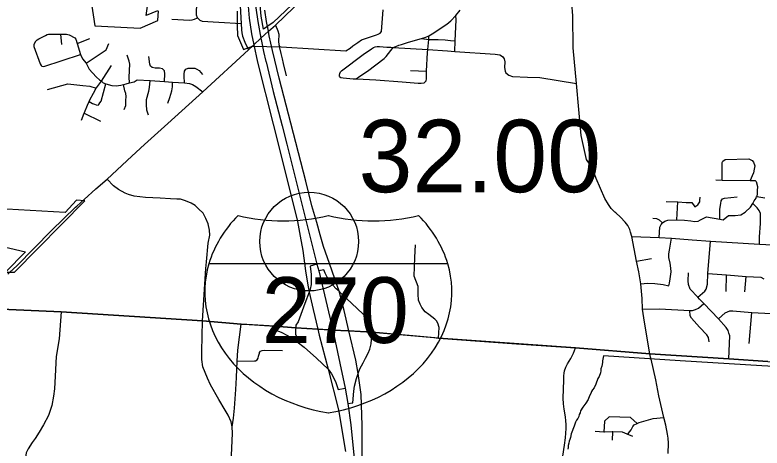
# Model space of a CAD drawing. Extents: x 1659811 to 1934326, y 644115 to 934867.
# Drawn here: x 1850731 to 1862074, y 747771 to 754351 of the extents above; entities that cross this region are included whole.
import ezdxf

# ---------------------------------------------------------------- set-up
doc = ezdxf.new("R2010")
doc.units = 0
for name, color, linetype in [('Default', 7, 'Continuous'), ('GM_X_City_Street', 7, 'Continuous'), ('GM_X_Corporation', 7, 'Continuous'), ('GM_X_County_Road', 7, 'Continuous'), ('GM_X_Interchange_Ramps', 7, 'Continuous'), ('GM_X_Interstate_Route', 7, 'Continuous'), ('GM_X_Interstate_Shield', 7, 'Continuous'), ('GM_X_Township', 7, 'Continuous'), ('GM_X_Township_Road', 7, 'Continuous')]:
    doc.layers.add(name, color=color, linetype=linetype)

msp = doc.modelspace()

# ---------------------------------------------------------------- linework, layer by layer
at = {"layer": 'Default'}
msp.add_circle((1855198, 750908), 750, dxfattribs=at)
at = {"layer": 'GM_X_City_Street'}
for points in [[(1853501, 754308), (1853490, 754346), (1853488, 754401), (1853507, 754810)], [(1859454, 752088), (1859408, 752155), (1859329, 752517), (1859255, 753310), (1859205, 753850), (1859199, 754339), (1859170, 754729)], [(1855660, 753415), (1855658, 753435), (1855662, 753460), (1855674, 753485), (1855687, 753500), (1856020, 753750), (1856142, 753838), (1856175, 753856), (1856201, 753864), (1856231, 753871), (1856267, 753873), (1856375, 753863), (1856437, 753860), (1856475, 753856), (1856514, 753870), (1856561, 753891), (1856600, 753902), (1856706, 753937), (1856905, 753992), (1856971, 754015), (1857017, 754034), (1857063, 754065), (1857290, 754210), (1857351, 754263), (1857423, 754341), (1857489, 754425)], [(1853113, 754289), (1853379, 754274), (1853424, 754276), (1853458, 754288), (1853501, 754308)], [(1853501, 754308), (1853536, 754272), (1853575, 754257), (1853826, 754241), (1854164, 754221)], [(1857407, 753798), (1857413, 753956), (1857431, 754277), (1857423, 754341)], [(1851037, 753940), (1851069, 753975), (1851092, 753990), (1851196, 754040), (1851218, 754052), (1851239, 754059), (1851416, 754060), (1851430, 754060), (1851450, 754060), (1851512, 754061), (1851552, 754051), (1851639, 754002), (1851657, 753982), (1851676, 753919)], [(1851444, 753904), (1851430, 754060)], [(1851037, 753940), (1851020, 753898), (1851016, 753870), (1851115, 753608), (1851127, 753582), (1851141, 753574), (1851169, 753568), (1851725, 753751)], [(1851676, 753919), (1851867, 753992)], [(1856905, 753992), (1857016, 753980), (1857156, 753977), (1857265, 753972), (1857346, 753964), (1857413, 753956)], [(1856944, 753319), (1856973, 753351), (1856980, 753382), (1856980, 753496), (1856997, 753779), (1857002, 753825), (1857016, 753980), (1857017, 754034)], [(1851672, 751448), (1851780, 751548), (1851958, 751708), (1852129, 751858), (1852504, 752203), (1852698, 752381), (1853053, 752701), (1853583, 753183), (1854276, 753823), (1854317, 753861)], [(1851676, 753919), (1851725, 753751), (1851758, 753684), (1851810, 753616), (1851860, 753529), (1851965, 753413), (1852019, 753361), (1852043, 753343), (1852072, 753322), (1852112, 753306), (1852204, 753279), (1852270, 753274), (1852338, 753284), (1852377, 753292), (1852422, 753303), (1852472, 753321), (1852542, 753334), (1852588, 753366), (1852783, 753355), (1853000, 753341), (1853125, 753329), (1853303, 753320), (1853380, 753308), (1853425, 753293), (1853479, 753266), (1853583, 753183)], [(1851810, 753616), (1852117, 753819), (1852156, 753915)], [(1854852, 753425), (1854808, 753613), (1854793, 753682), (1854773, 753767), (1854746, 753869)], [(1855910, 753382), (1855968, 753420), (1856082, 753498), (1856335, 753688), (1856367, 753722), (1856475, 753856)], [(1856475, 753856), (1857002, 753825), (1857297, 753805), (1857407, 753798), (1858022, 753757), (1858091, 753746), (1858133, 753720), (1858157, 753685), (1858169, 753638), (1858165, 753550), (1858173, 753498), (1858184, 753472), (1858227, 753435), (1858284, 753418), (1858514, 753404), (1858700, 753400), (1859255, 753310)], [(1852472, 753321), (1852467, 753405), (1852477, 753601), (1852463, 753649), (1852434, 753740)], [(1853000, 753341), (1853008, 753455), (1853003, 753503), (1852972, 753531), (1852924, 753540), (1852861, 753542), (1852815, 753550), (1852789, 753573), (1852781, 753602), (1852762, 753722)], [(1852043, 753343), (1852195, 753582)], [(1853303, 753320), (1853300, 753420), (1853301, 753451), (1853307, 753499), (1853325, 753525), (1853360, 753540), (1853411, 753544), (1853460, 753540), (1853494, 753529), (1853529, 753507), (1853577, 753445)], [(1856737, 753506), (1856980, 753496)], [(1855660, 753415), (1855681, 753403), (1855715, 753393), (1855866, 753379), (1855910, 753382), (1856017, 753375), (1856211, 753364), (1856610, 753337), (1856853, 753316), (1856899, 753312), (1856944, 753319)], [(1851225, 753218), (1851532, 753305), (1851762, 753279), (1851870, 753268), (1851966, 753236)], [(1851743, 752752), (1851783, 752858), (1851788, 752870), (1851831, 752982), (1851858, 753037), (1851870, 753062), (1851923, 753161), (1851966, 753236), (1851971, 753245), (1852043, 753343)], [(1851858, 753037), (1851911, 753007), (1851941, 752995), (1851963, 752983), (1851995, 752980), (1852007, 752992), (1852019, 753018), (1852039, 753042), (1852112, 753306)], [(1852390, 752914), (1852413, 752974), (1852417, 753052), (1852422, 753114), (1852413, 753159), (1852399, 753197), (1852377, 753292)], [(1852758, 752830), (1852734, 752904), (1852730, 752988), (1852731, 753067), (1852762, 753192), (1852775, 753250), (1852783, 753355)], [(1853050, 753012), (1853082, 753097), (1853113, 753196), (1853121, 753260), (1853125, 753329)], [(1851783, 752858), (1852032, 752735)], [(1861469, 751843), (1861470, 752089), (1861470, 752111), (1861476, 752131)], [(1861476, 752131), (1861512, 752157), (1861872, 752166), (1861924, 752140), (1861946, 752114), (1861964, 752056), (1861954, 752006), (1861944, 751953), (1861924, 751909), (1861893, 751837)], [(1859856, 751343), (1859841, 751356), (1859784, 751411), (1859741, 751473), (1859687, 751564), (1859557, 751865), (1859494, 752031), (1859454, 752088)], [(1853639, 750599), (1853664, 750886), (1853690, 751006), (1853683, 751080), (1853665, 751175), (1853629, 751256), (1853589, 751337), (1853517, 751404), (1853467, 751455), (1853409, 751489), (1853323, 751529), (1853247, 751553), (1853190, 751550), (1853093, 751557), (1852936, 751567), (1852712, 751578), (1852541, 751597), (1852453, 751621), (1852405, 751644), (1852304, 751700), (1852229, 751753), (1852129, 751858)], [(1861374, 751844), (1861469, 751843), (1861893, 751837), (1861968, 751836), (1861985, 751822), (1862006, 751745), (1862001, 751681), (1861997, 751639), (1861992, 751595)], [(1860543, 751169), (1860564, 751194), (1860597, 751217), (1860641, 751231), (1860780, 751236), (1860897, 751233), (1860992, 751223), (1861048, 751212), (1861102, 751220), (1861140, 751237), (1861230, 751286), (1861433, 751249), (1861485, 751240), (1861564, 751304), (1861667, 751302), (1861752, 751316), (1861819, 751353), (1861898, 751433), (1861936, 751485), (1861953, 751526), (1861984, 751569), (1861988, 751595), (1861992, 751595), (1862118, 751571)], [(1860618, 751519), (1860793, 751510), (1860920, 751500), (1861007, 751502), (1861054, 751434), (1861100, 751465), (1861108, 751479), (1861129, 751513), (1861127, 751537), (1861136, 751581)], [(1861433, 751249), (1861435, 751401), (1861449, 751487), (1861455, 751527), (1861474, 751556), (1861504, 751568), (1861696, 751589)], [(1860780, 751236), (1860793, 751510)], [(1862049, 751272), (1862049, 751336), (1862032, 751378), (1862001, 751420), (1861936, 751485)], [(1860368, 749204), (1860290, 749682), (1860261, 749882), (1860255, 750045), (1860234, 750267), (1860205, 750447), (1860168, 750610), (1860095, 750987), (1860077, 751049), (1860066, 751089), (1860034, 751150), (1859996, 751202), (1859924, 751279), (1859856, 751343)], [(1860564, 751194), (1860519, 751233), (1860474, 751253), (1860416, 751256)], [(1862037, 750868), (1862033, 750982), (1862050, 751182), (1862049, 751272)], [(1860510, 750971), (1860521, 751129), (1860535, 751159), (1860543, 751169)], [(1860095, 750987), (1860510, 750971), (1860699, 750957), (1861015, 750936), (1861290, 750914), (1862037, 750868), (1862619, 750836), (1863241, 750810), (1864452, 750722), (1864480, 750720)], [(1860658, 750237), (1860669, 750274), (1860679, 750341), (1860695, 750450), (1860691, 750503), (1860679, 750582), (1860658, 750665), (1860656, 750722), (1860666, 750779), (1860699, 750957)], [(1861099, 750062), (1861203, 750154), (1861225, 750185), (1861244, 750263), (1861252, 750422), (1861290, 750914)], [(1857164, 749442), (1857173, 749601), (1857150, 749668), (1857130, 749702), (1857107, 749727), (1857015, 749799), (1856961, 749842), (1856908, 749905), (1856881, 749956), (1856858, 750017), (1856851, 750107), (1856855, 750227), (1856793, 750384), (1856802, 750666), (1856811, 750860)], [(1860168, 750610), (1860394, 750650)], [(1853581, 749702), (1853581, 749702), (1853631, 750497), (1853639, 750599)], [(1861125, 750034), (1861099, 750062), (1860983, 750185), (1860956, 750254), (1860953, 750310), (1860956, 750435)], [(1861252, 750422), (1861536, 750401), (1861831, 750379), (1862056, 750365), (1862102, 750343)], [(1861527, 750151), (1861536, 750401)], [(1861813, 750142), (1861831, 750379)], [(1860234, 750267), (1860334, 750277), (1860447, 750271), (1860571, 750256), (1860658, 750237)], [(1860261, 749882), (1860515, 749884), (1860979, 749861), (1861017, 749863), (1861062, 749877), (1861110, 749898), (1861191, 749965)], [(1861564, 749535), (1861557, 749556), (1861527, 749602), (1861410, 749733), (1861191, 749965), (1861125, 750034)], [(1850164, 749899), (1850178, 749898), (1851432, 749838), (1853581, 749702), (1854164, 749653), (1854211, 749651)], [(1861271, 749383), (1861259, 749449), (1861234, 749489), (1861122, 749607), (1861000, 749744), (1860984, 749781), (1860979, 749861)], [(1861410, 749733), (1861515, 749824), (1861582, 749853), (1861630, 749856), (1861920, 749832), (1862212, 749816)], [(1851432, 749838), (1851405, 749428), (1851356, 749164), (1851343, 748864), (1851333, 748672), (1851315, 748559), (1851290, 748415), (1851241, 748265), (1851165, 748123), (1851097, 748013), (1851039, 747917), (1850993, 747855), (1850933, 747761), (1850903, 747696), (1850893, 747632), (1850888, 747450), (1850873, 747113), (1850864, 746855), (1850853, 746374), (1850846, 746224), (1850838, 745952), (1850846, 745706), (1850886, 745480), (1850900, 745441)], [(1861879, 749358), (1861920, 749832)], [(1853922, 748347), (1853827, 748510), (1853700, 748733), (1853654, 748831), (1853585, 749004), (1853571, 749118), (1853568, 749238), (1853581, 749702)], [(1854028, 748094), (1854048, 748224), (1854064, 748375), (1854086, 748661), (1854095, 748841), (1854106, 749091), (1854114, 749260), (1854164, 749653)], [(1854211, 749651), (1854678, 749625), (1854995, 749599)], [(1854995, 749599), (1855330, 749578), (1855521, 749565)], [(1855521, 749565), (1855559, 749563), (1855798, 749550), (1856152, 749530), (1856204, 749525)], [(1856204, 749525), (1856569, 749494)], [(1861567, 749127), (1861582, 749475), (1861570, 749517), (1861564, 749535)], [(1856569, 749494), (1857091, 749448)], [(1857091, 749448), (1857164, 749442), (1858345, 749356)], [(1858345, 749356), (1859239, 749292), (1860368, 749204), (1861567, 749127), (1862160, 749085), (1862472, 749064), (1863172, 749017), (1865082, 748902), (1866053, 748847)], [(1859050, 747649), (1859073, 747815), (1859088, 747928), (1859095, 747999), (1859099, 748067), (1859100, 748127), (1859097, 748185), (1859092, 748246), (1859071, 748360), (1859059, 748442), (1859056, 748531), (1859063, 748801), (1859066, 748867), (1859071, 748906), (1859075, 748943), (1859094, 749001), (1859119, 749052), (1859171, 749131), (1859210, 749211), (1859239, 749292)], [(1854368, 749095), (1854381, 749095), (1854407, 749111), (1854422, 749135), (1854431, 749165), (1854442, 749211), (1854445, 749223), (1854459, 749241), (1854485, 749254), (1854518, 749260), (1854794, 749251)], [(1860380, 749153), (1860368, 749204)], [(1854106, 749091), (1854368, 749095)], [(1860648, 747687), (1860652, 747847), (1860647, 747922), (1860638, 747982), (1860611, 748117), (1860581, 748234), (1860508, 748565), (1860459, 748809), (1860388, 749123), (1860380, 749153)], [(1853953, 746027), (1853963, 746238), (1854012, 747167), (1854020, 747660), (1854033, 747996), (1854028, 748094), (1854012, 748171), (1853967, 748271), (1853922, 748347)], [(1860180, 748145), (1860077, 748233), (1859754, 748244), (1859680, 748177), (1859674, 748012)], [(1860026, 747984), (1860044, 747998), (1860084, 748046), (1860114, 748100), (1860134, 748125), (1860180, 748145), (1860208, 748157), (1860420, 748220), (1860581, 748234)], [(1860114, 747945), (1860026, 747984), (1859954, 748014), (1859808, 748017), (1859797, 748017), (1859680, 748012), (1859674, 748012), (1859541, 748022)], [(1859805, 747889), (1859808, 748017)]]:
    msp.add_lwpolyline(points, dxfattribs=at)
at = {"layer": 'GM_X_Corporation'}
for points in [[(1854936, 754505), (1854651, 754237), (1854503, 754137), (1854469, 754330), (1854427, 754783)], [(1852895, 754413), (1852722, 754343), (1852772, 754709)], [(1851884, 754592), (1851946, 754187), (1852044, 754181), (1852632, 754149), (1852903, 754266), (1852912, 754411)], [(1854106, 754408), (1854107, 754185), (1854108, 754041), (1854200, 753825), (1854336, 753879), (1854772, 753868), (1855753, 753806), (1855820, 753844), (1855860, 753881), (1855890, 753902), (1855938, 753933), (1855993, 753971), (1856127, 754018), (1856160, 754031), (1856189, 754039), (1856218, 754051), (1856247, 754060), (1856277, 754076), (1856297, 754101), (1856321, 754431)], [(1863089, 748962), (1862072, 749022), (1860830, 749095), (1859666, 749172), (1859651, 749098), (1859651, 749070), (1859639, 749013), (1859628, 748972), (1859628, 748944), (1859622, 748915), (1859599, 748858), (1859582, 748829), (1859548, 748743), (1859525, 748686), (1859502, 748657), (1859485, 748629), (1859473, 748600), (1859456, 748566), (1859433, 748509), (1859399, 748451), (1859353, 748394), (1859319, 748337), (1859313, 748308), (1859296, 748279), (1859290, 748251), (1859279, 748222), (1859256, 748194), (1859239, 748165), (1859233, 748136), (1859221, 748102), (1859176, 747987), (1859164, 747930), (1859153, 747901), (1859147, 747873), (1859141, 747844), (1859130, 747810), (1859130, 747781), (1859124, 747753)]]:
    msp.add_lwpolyline(points, dxfattribs=at)
msp.add_lwpolyline([(1849718, 751453), (1849718, 751327), (1849725, 751300), (1849722, 751274), (1849728, 751244), (1849728, 751218), (1849732, 751191), (1849732, 751161), (1849738, 751135), (1849741, 751108), (1849741, 751082), (1849745, 751055), (1849763, 751013), (1850889, 750754), (1850587, 750443), (1850724, 750443), (1851794, 751528), (1851667, 751535), (1851494, 751348)], close=True, dxfattribs=at)
at = {"layer": 'GM_X_County_Road'}
for points in [[(1854317, 753861), (1854359, 753899), (1854464, 753996), (1854579, 754103), (1854687, 754196), (1854967, 754466), (1855029, 754523)], [(1850625, 750413), (1850654, 750442), (1850761, 750538), (1851287, 751075), (1851650, 751428), (1851672, 751448)]]:
    msp.add_lwpolyline(points, dxfattribs=at)
at = {"layer": 'GM_X_Interchange_Ramps'}
for points in [[(1854262, 754611), (1854288, 754302), (1854324, 754065), (1854359, 753899), (1854414, 753631), (1854649, 752693), (1854933, 751563), (1855020, 751211), (1855063, 750991), (1855100, 750774), (1855144, 750461), (1855171, 750278), (1855198, 750140), (1855257, 749875), (1855330, 749578), (1855348, 749488), (1855487, 748967), (1855643, 748349), (1855749, 747720)], [(1856003, 747647), (1856002, 748113), (1855989, 748584), (1855944, 748902), (1855908, 749105), (1855798, 749550), (1855727, 749862), (1855651, 750152), (1855588, 750343), (1855509, 750573), (1855415, 750834), (1855363, 751011), (1855312, 751198), (1855239, 751451), (1855147, 751826), (1854886, 752844), (1854744, 753388), (1854643, 753809), (1854593, 754032), (1854579, 754103), (1854548, 754252), (1854524, 754424)], [(1855316, 750564), (1855214, 750535), (1855228, 750405), (1855226, 750257), (1855213, 750185), (1855198, 750140), (1855134, 749967), (1855030, 749690), (1854998, 749637), (1854995, 749599)], [(1856152, 749530), (1856151, 749564), (1856149, 749626), (1856139, 749662), (1856127, 749690), (1856110, 749715), (1856080, 749747), (1856014, 749808), (1855681, 750126), (1855651, 750152), (1855607, 750190), (1855513, 750294), (1855473, 750366), (1855441, 750428), (1855420, 750480), (1855343, 750461)], [(1854678, 749625), (1854675, 749568), (1854775, 749531), (1854870, 749483), (1855016, 749387), (1855123, 749306), (1855309, 749134), (1855487, 748967), (1855538, 748900), (1855600, 748781), (1855637, 748658), (1855743, 748680)], [(1854995, 749599), (1854993, 749576), (1854990, 749534), (1854992, 749502), (1854999, 749475), (1855014, 749445), (1855033, 749408), (1855016, 749387)], [(1855787, 748448), (1855862, 748457), (1855876, 748637), (1855887, 748712), (1855918, 748827), (1855944, 748902), (1855968, 748972), (1856018, 749068), (1856052, 749135), (1856092, 749212), (1856117, 749274), (1856137, 749356), (1856148, 749489), (1856152, 749530)]]:
    msp.add_lwpolyline(points, dxfattribs=at)
at = {"layer": 'GM_X_Interstate_Route'}
for points in [[(1854362, 754845), (1854377, 754623), (1854389, 754459), (1854419, 754250), (1854464, 753996), (1854473, 753953)], [(1854473, 753953), (1854506, 753797), (1854542, 753643)], [(1854542, 753643), (1854543, 753636), (1854654, 753187), (1854786, 752668)], [(1854786, 752668), (1854857, 752389), (1855316, 750564), (1855343, 750461), (1855559, 749563)], [(1855559, 749563), (1855666, 749062), (1855743, 748680), (1855787, 748448), (1855832, 748122), (1855889, 747513), (1855913, 746894), (1855910, 746218), (1855867, 745511), (1855827, 744875), (1855781, 744012), (1855679, 742509)]]:
    msp.add_lwpolyline(points, dxfattribs=at)
at = {"layer": 'GM_X_Interstate_Shield'}
msp.add_line((1857302, 750570), (1853676, 750570), dxfattribs=at)
msp.add_line((1857302, 750570), (1853676, 750570), dxfattribs=at)
for centre, start_param, end_param in [((1855958, 750142), 2.47259, 2.911027), ((1854804, 753098), 4.415841, 5.008937), ((1856174, 753098), 4.415841, 5.008937), ((1855020, 750142), 0.230566, 0.669003), ((1855958, 750142), 2.911027, 4.511031), ((1855020, 750142), 4.913747, 6.513751)]:
    msp.add_ellipse(centre, major_axis=(2344, 0), ratio=0.8, start_param=start_param, end_param=end_param, dxfattribs=at)
at = {"layer": 'GM_X_Township'}
msp.add_lwpolyline([(1862160, 749085), (1861567, 749127), (1860368, 749204), (1859239, 749292), (1857164, 749442), (1856152, 749530), (1855788, 749550), (1855559, 749563), (1855330, 749578), (1854995, 749599), (1854678, 749625), (1854164, 749653), (1853581, 749702), (1851432, 749838), (1850178, 749898), (1848956, 749976), (1847649, 750064), (1846056, 750164), (1844025, 750293)], dxfattribs=at)
at = {"layer": 'GM_X_Township_Road'}
for points in [[(1852703, 754865), (1853214, 754839), (1853507, 754810), (1853851, 754791), (1853987, 754780), (1854044, 754778), (1854076, 754720), (1854109, 754669), (1854125, 754633), (1854141, 754568), (1854148, 754491), (1854164, 754221), (1854172, 754126), (1854177, 754081), (1854188, 754027), (1854222, 753939), (1854276, 753823)], [(1854687, 754196), (1854724, 754108), (1854738, 754058), (1854736, 754022), (1854734, 753984), (1854732, 753945), (1854738, 753900), (1854746, 753869)]]:
    msp.add_lwpolyline(points, dxfattribs=at)

# ---------------------------------------------------------------- texts
at = {"layer": 'Default'}
msp.add_text('32.00', height=1100, dxfattribs=at).set_placement((1855948, 751658))
at = {"layer": 'GM_X_Interstate_Shield'}
msp.add_text('270', height=1000, dxfattribs=at).set_placement((1854479, 749367))

doc.saveas('drawing.dxf')
